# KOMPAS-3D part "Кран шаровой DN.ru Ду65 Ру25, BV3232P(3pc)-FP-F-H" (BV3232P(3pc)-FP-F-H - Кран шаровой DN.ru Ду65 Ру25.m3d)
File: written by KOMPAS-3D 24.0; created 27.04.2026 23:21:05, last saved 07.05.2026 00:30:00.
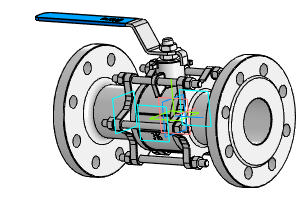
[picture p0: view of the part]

Document properties: Автор: Максим; Полное имя файла: BVxxP(3pc)-FP-F-H - Кран шаровой DN.ru Ду65 Ру25.cdw

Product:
- Body: Тело 1  | qty 1
    Масса: 13.766972
- Part/product: Кран шаровой DN.ru Ду65 Ру25  | designation BV3232P(3pc)-FP-F-H
    Масса: 12.445
    Раздел спецификации: Прочие изделия
    Форматы листов документа: A3
    Примечание: D160-22807

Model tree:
1. Операция без истории:1
2. Эскиз:1  (with: Ребро.Операция без истории:1)
3. Элемент выдавливания:1
     Расстояние 1 = 12
4. Эскиз:2  (with: Грань.Операция без истории:1)
5. Элемент выдавливания:2
     Расстояние 1 = 9; Расстояние 2 = 50
6. Эскиз:3  (with: Грань.Элемент выдавливания:2)
7. Элемент выдавливания:3  (with: Грань.Операция без истории:1)
     Расстояние 1 = 50
8. Эскиз:4  (with: Грань.Операция без истории:1)
9. Элемент выдавливания:4
     Расстояние 1 = 8
10. Фаска:1  (with: Ребро.Элемент выдавливания:4)
     Угол = 45; Длина 1 = 2; Длина 2 = 2
11. Скругление:1  (with: Ребро.Элемент выдавливания:1)
     Радиус = 4
12. Скругление:2  (with: Ребро.Элемент выдавливания:1)
     Радиус = 8
13. Эскиз:5  (with: Ребро.Элемент выдавливания:1, Ребро.Элемент выдавливания:3)
14. Элемент выдавливания:5
     Расстояние 1 = 31
15. Фаска:2  (with: Ребро.Элемент выдавливания:5)
     Угол = 45; Длина 1 = 8; Длина 2 = 8
16. Скругление:3  (with: Грань.Операция без истории:1, Ребро.Элемент выдавливания:1)
     Радиус = 4
17. Скругление:4  (with: Ребро.Элемент выдавливания:1)
     Радиус = 8
18. Эскиз:6  (with: Ребро.Элемент выдавливания:5)
19. Элемент выдавливания:6
     Расстояние 1 = 32
20. Скругление:5  (with: Ребро.Элемент выдавливания:6)
     Радиус = 10
21. Скругление:6  (with: Ребро.Элемент выдавливания:6)
     Радиус = 0.5
22. Эскиз:7  (with: Грань.Операция без истории:1, Ребро.Операция без истории:1)
23. Элемент выдавливания:7  (with: Грань.Операция без истории:1)
     Расстояние 2 = 290
24. Смещенная плоскость:1
     Расстояние = -86
25. Эскиз:8  (with: Ребро.Операция без истории:1)
26. Элемент выдавливания:8
     Расстояние 1 = 38
27. Зеркальный массив:1
28. Экземпляр ( 1 )
29. Экземпляр ( 2 )  (with: Элемент выдавливания:8)
30. Смещенная плоскость:2
     Расстояние = -49
31. Эскиз:9
32. Элемент выдавливания:9  (with: Грань.Операция без истории:1)
     Расстояние 1 = -4.69762
33. Эскиз:10  (with: Ребро.Операция без истории:1)
34. Элемент выдавливания:10
     Расстояние 1 = 39
35. Эскиз:11  (with: Ребро.Скругление:3, Грань.Операция без истории:1)
36. Элемент вращения:1
     Угол 1 = 360
37. Фаска:3
     Угол = 45; Длина 1 = 1; Длина 2 = 1
38. Смещенная плоскость:3
     Расстояние = 49
39. Эскиз:12
40. Элемент выдавливания:11  (with: Грань.Операция без истории:1)
     Расстояние 1 = -5.40968
41. Зеркальный массив:2  (with: Экземпляр ( 1 ), Экземпляр ( 2 ), Элемент выдавливания:10)
42. Эскиз:13  (with: Грань.Элемент выдавливания:6, Ребро.Скругление:6, Ребро.Элемент выдавливания:6)
43. Элемент выдавливания:12
     Расстояние 2 = 0.2

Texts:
  BV3232P(3pc)-FP-F-H
  DN65 PN25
